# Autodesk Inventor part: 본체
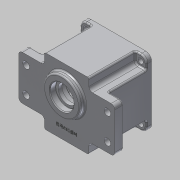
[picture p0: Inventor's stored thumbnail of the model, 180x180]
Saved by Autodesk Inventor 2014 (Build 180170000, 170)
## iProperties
Created: 2014-12
Part Number: 본체
Material: 알루미늄 6061
Document SubType Name: Modeling
Designer: user
Density: 2.71 g/cm^3
Appearance: 알루미늄 - 평지
Mass: 705.361 g
Surface Area: 672.962 cm^2
Volume: 260.281 cm^3
Author: user
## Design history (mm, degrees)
sketch "스케치2"
  geometry: L1 (-45, -45)-(45, -45); L2 (45, -45)-(45, 45); L3 (45, 45)-(-45, 45); L4 (-45, 45)-(-45, -45); L5 (-45, -45)-(45, 45); L6 (45, -45)-(-45, 45); 1 further point
  constraints: 12 end point, 2 midpoint, 2 parallel, 1 horizontal, 1 perpendicular
  dimensions: "d0" = 90 distance of L2.end L3.end; "d1" = 90 distance of L1.end L2.end
extrude "돌출1" new body sketch "스케치2" distance "d2" = 70; taper "d3" = 0 deg
sketch "스케치3"
  geometry: L1 (-65, -30)-(65, -30); L2 (65, -30)-(65, 30); L3 (65, 30)-(-65, 30); L4 (-65, 30)-(-65, -30); L5 (-65, -30)-(65, 30); L6 (65, -30)-(-65, 30); 1 further point
  constraints: 12 end point, 2 midpoint, 2 parallel, 1 horizontal, 1 perpendicular
  dimensions: "d4" = 130 distance of L2.end L3.end; "d5" = 60 distance of L1.end L2.end
extrude "돌출2" join sketch "스케치3" distance "d6" = 12; taper "d7" = 0 deg
sketch "스케치4"
  geometry: L1 (-45, 45)-(-30, 45); L2 (-30, 45)-(-30, 30); L3 (-30, 30)-(-45, 30); L4 (-45, 30)-(-45, 45); L5 (45, 45)-(30, 45); L6 (30, 45)-(30, 30); L7 (30, 30)-(45, 30); L8 (45, 30)-(45, 45); L9 (45, -45)-(30, -45); L10 (30, -45)-(30, -30); L11 (30, -30)-(45, -30); L12 (45, -30)-(45, -45); L13 (-45, -45)-(-30, -45); L14 (-30, -45)-(-30, -30); L15 (-30, -30)-(-45, -30); L16 (-45, -30)-(-45, -45); 1 further point
  constraints: 32 end point, 8 parallel, 4 horizontal, 4 perpendicular
  dimensions: "d8" = 15 distance of L1.start L1.end; "d9" = 15 distance of L1.end L2.end; "d10" = 15 distance of L5.start L5.end; "d11" = 15 distance of L5.end L6.end; "d12" = 15 distance of L11.end L9.start; "d13" = 15 distance of L9.start L9.end; "d14" = 15 distance of L13.start L13.end; "d15" = 15 distance of L15.end L13.start
extrude "돌출3" cut sketch "스케치4" distance "d16" = 63; taper "d17" = 0 deg
fillet "모깎기1" dims "d18" = 8
fillet "모깎기2" dims "d19" = 5
fillet "모깎기3" dims "d20" = 2
sketch "스케치5"
  geometry: L1 (-37, -37)-(37, -37); L2 (37, -37)-(37, 37); L3 (37, 37)-(-37, 37); L4 (-37, 37)-(-37, -37); L5 (-37, -37)-(37, 37); L6 (37, -37)-(-37, 37); 5 further points
  constraints: 12 end point, 4 coincident, 2 midpoint, 2 parallel, 1 horizontal, 1 perpendicular
  dimensions: "d21" = 74 distance of L2.end L3.end; "d22" = 74 distance of L1.end L2.end
hole "구멍1" sketch "스케치5" at (-37, 37), (37, 37), (37, -37), (-37, -37) diameter "d23" = 7; stored, may be unused: countersink angle "d27" = 90 deg, drill point angle "d29" = 118 deg; dims "d24" = 6, "d25" = 4, "d26" = 2, "d28" = 8
sketch "스케치6"
  geometry: L1 (-55, -17.5)-(55, -17.5); L2 (55, -17.5)-(55, 17.5); L3 (55, 17.5)-(-55, 17.5); L4 (-55, 17.5)-(-55, -17.5); L5 (-55, -17.5)-(55, 17.5); L6 (55, -17.5)-(-55, 17.5); 5 further points
  constraints: 12 end point, 4 coincident, 2 midpoint, 2 parallel, 1 horizontal, 1 perpendicular
  dimensions: "d30" = 110 distance of L2.end L3.end; "d31" = 35 distance of L1.end L2.end
hole "구멍2" sketch "스케치6" at (-55, 17.5), (-55, -17.5), (55, 17.5), (55, -17.5) diameter "d32" = 9; stored, may be unused: countersink angle "d36" = 90 deg, drill point angle "d38" = 118 deg; dims "d33" = 6, "d34" = 4, "d35" = 2, "d37" = 8
sketch "스케치7"
  geometry: C1 r 25 at (0, 11); 1 further point
  constraints: 1 centre point, 1 vertical alignment
  dimensions: "d39" = 50 diameter of C1; "d40" = 11 distance of point (0, 0) C1.centre
extrude "돌출4" join sketch "스케치7" distance "d41" = 7; taper "d42" = 0 deg
fillet "모깎기4" dims "d43" = 2
sketch "스케치8"
  geometry: C1 r 40 at (0, 0); 1 further point
  constraints: 1 centre point, 1 coincident
  dimensions: "d44" = 80 diameter of C1
extrude "돌출5" cut sketch "스케치8" distance "d45" = 9; taper "d46" = 0 deg
sketch "스케치9"
  geometry: C1 r 40 at (0, 0) reference; C2 r 39 at (0, 0)
  constraints: 1 centre point, 1 coincident
  dimensions: "d47" = 78 diameter of C2
extrude "돌출6" cut sketch "스케치9" distance "d48" = 52; taper "d49" = 0 deg
sketch "스케치10" dims "d50" = 70
  geometry: L1 (24.749, 24.749)-(-24.749, -24.749); L2 (-24.749, 24.749)-(24.749, -24.749); L3 (-35, 0)-(35, 0); C1 r 39 at (0, 0) reference; A1 r 4 centre (24.749, 24.749) between (21.809, 27.462) and (27.462, 21.809); A2 r 4 centre (-24.749, 24.749) between (-27.462, 21.809) and (-21.809, 27.462); A3 r 4 centre (24.749, -24.749) between (27.462, -21.809) and (21.809, -27.462); A4 r 4 centre (-24.749, -24.749) between (-21.809, -27.462) and (-27.462, -21.809); A5 r 3.5 centre (-19.238, -29.836) between (-15.988, -31.135) and (-21.762, -27.412); A6 r 3.5 centre (-29.836, -19.238) between (-31.135, -15.988) and (-32.777, -21.134); A7 r 3.5 centre (19.238, -29.836) between (15.988, -31.135) and (21.134, -32.777); A8 r 3.5 centre (29.836, -19.238) between (27.412, -21.762) and (32.777, -21.134); A9 r 3.5 centre (29.836, 19.238) between (31.135, 15.988) and (32.777, 21.134); A10 r 3.5 centre (19.238, 29.836) between (15.988, 31.135) and (21.762, 27.412); A11 r 3.5 centre (-19.238, 29.836) between (-21.134, 32.777) and (-21.762, 27.412); A12 r 3.5 centre (-29.836, 19.238) between (-27.412, 21.762) and (-32.777, 21.134); A13 r 3.5 centre (-19.238, 29.836) between (-15.988, 31.135) and (-21.134, 32.777); A14 r 3.5 centre (-19.238, 29.836) between (-21.762, 27.412) and (-15.988, 31.135); A15 r 4 centre (-24.749, 24.749) between (-27.577, 27.577) and (-27.462, 21.809); A16 r 3.5 centre (-29.836, 19.238) between (-31.135, 15.988) and (-27.412, 21.762); A17 r 3.5 centre (-29.836, 19.238) between (-32.777, 21.134) and (-31.135, 15.988); A18 r 39 centre (0, 0) between (-32.777, 21.134) and (-32.777, -21.134); A19 r 39 centre (0, 0) between (-21.134, 32.777) and (-32.777, 21.134); A20 r 3.5 centre (19.238, 29.836) between (21.134, 32.777) and (15.988, 31.135); A21 r 3.5 centre (19.238, 29.836) between (21.762, 27.412) and (21.134, 32.777); A22 r 4 centre (24.749, 24.749) between (27.577, 27.577) and (21.809, 27.462); A23 r 4 centre (24.749, 24.749) between (27.462, 21.809) and (27.577, 27.577); A24 r 3.5 centre (29.836, 19.238) between (27.412, 21.762) and (31.135, 15.988); A25 r 3.5 centre (29.836, 19.238) between (32.777, 21.134) and (27.412, 21.762); A26 r 3.5 centre (29.836, -19.238) between (31.135, -15.988) and (27.412, -21.762); A27 r 3.5 centre (29.836, -19.238) between (32.777, -21.134) and (31.135, -15.988); A28 r 4 centre (24.749, -24.749) between (27.577, -27.577) and (27.462, -21.809); A29 r 4 centre (24.749, -24.749) between (21.809, -27.462) and (27.577, -27.577); A30 r 3.5 centre (19.238, -29.836) between (21.762, -27.412) and (15.988, -31.135); A31 r 3.5 centre (19.238, -29.836) between (21.134, -32.777) and (21.762, -27.412); A32 r 39 centre (0, 0) between (21.134, -32.777) and (32.777, -21.134); A33 r 3.5 centre (-19.238, -29.836) between (-21.134, -32.777) and (-15.988, -31.135); A34 r 3.5 centre (-19.238, -29.836) between (-21.762, -27.412) and (-21.134, -32.777); A35 r 4 centre (-24.749, -24.749) between (-27.577, -27.577) and (-21.809, -27.462); A36 r 4 centre (-24.749, -24.749) between (-27.462, -21.809) and (-27.577, -27.577); A37 r 3.5 centre (-29.836, -19.238) between (-27.412, -21.762) and (-31.135, -15.988); A38 r 3.5 centre (-29.836, -19.238) between (-32.777, -21.134) and (-27.412, -21.762); A39 r 39 centre (0, 0) between (-21.134, -32.777) and (21.134, -32.777); A40 r 39 centre (0, 0) between (32.777, -21.134) and (39, 0); A41 r 39 centre (0, 0) between (32.777, 21.134) and (27.577, 27.577); A42 r 39 centre (0, 0) between (39, 0) and (32.777, 21.134); A43 r 39 centre (0, 0) between (27.577, 27.577) and (-21.134, 32.777); A44 r 4 centre (-24.749, 24.749) between (-21.809, 27.462) and (-27.577, 27.577); 3 further points
  constraints: 111 point on circle, 44 centre point, 16 tangent, 7 coincident, 6 end point, 4 midpoint, 1 horizontal, 1 point on line, 35 other
  dimensions: "d51" = 45 deg angle of L3 L1; "d52" = 90 deg angle of L2 L1; "d53" = 8 diameter of A1; "d54" = 8 diameter of A2; "d57" = 8 diameter of A3; "d58" = 8 diameter of A4; "d59" = 7 diameter of A6; "d60" = 7 diameter of A5; "d61" = 7 diameter of A7; "d62" = 7 diameter of A8; "d63" = 7 diameter of A9; "d64" = 7 diameter of A10; "d65" = 7 diameter of A11; "d66" = 7 diameter of A12
extrude "돌출7" join sketch "스케치10" distance "d67" = 52; taper "d68" = 0 deg
sketch "스케치11"
  geometry: A1 r 4 centre (24.749, -24.749) between (27.462, -21.809) and (21.809, -27.462) reference; A2 r 4 centre (-24.749, -24.749) between (-21.809, -27.462) and (-27.462, -21.809) reference; A3 r 4 centre (-24.749, 24.749) between (-27.462, 21.809) and (-21.809, 27.462) reference; A4 r 4 centre (24.749, 24.749) between (21.809, 27.462) and (27.462, 21.809) reference; 4 further points
  constraints: 4 coincident
hole "구멍3" sketch "스케치11" at (-24.749, 24.749), (24.749, 24.749), (24.749, -24.749), (-24.749, -24.749) diameter "d69" = 3.459; stored, may be unused: countersink angle "d73" = 90 deg, drill point angle "d75" = 118 deg; dims "d70" = 12, "d71" = 4, "d72" = 2, "d74" = 15
sketch "스케치12"
  geometry: A1 r 39 centre (0, 0) between (-32.777, 21.134) and (-32.777, -21.134) reference; A2 r 20.5 centre (0, -11) between (-7.402, 8.117) and (7.402, 8.117); A3 r 14 centre (0, 20) between (7.402, 8.117) and (-7.402, 8.117); A4 r 14 centre (0, 20) between (-7.402, 8.117) and (7.402, 8.117); A5 r 20.5 centre (0, -11) between (7.402, 8.117) and (-7.402, 8.117)
  constraints: 8 point on circle, 4 centre point, 2 vertical alignment
  dimensions: "d76" = 41 diameter of A2; "d77" = 28 diameter of A3; "d78" = 11 distance of A1.centre A2.centre; "d79" = 20 distance of A1.centre A3.centre
extrude "돌출8" join sketch "스케치12" distance "d80" = 7; taper "d81" = 0 deg
fillet "모깎기5" dims "d82" = 3
sketch "스케치13"
  geometry: C1 r 17.5 at (0, -11); A1 r 20.5 centre (0, -11) between (-11.115, 6.225) and (11.115, 6.225) reference; 1 further point
  constraints: 1 centre point, 1 coincident
  dimensions: "d83" = 35 diameter of C1
extrude "돌출9" cut sketch "스케치13" distance "d84" = 10; taper "d85" = 0 deg
sketch "스케치14"
  geometry: C1 r 17.5 at (0, 0) reference; C2 r 12.5 at (0, 0); 1 further point
  constraints: 1 centre point, 1 coincident
  dimensions: "d86" = 25 diameter of C2
extrude "돌출10" cut sketch "스케치14" distance "d87" = 5; taper "d88" = 0 deg
sketch "스케치15"
  geometry: C1 r 23 at (0, 0) reference; C2 r 16 at (0, 0); 1 further point
  constraints: 1 centre point, 1 coincident
  dimensions: "d89" = 32 diameter of C2
extrude "돌출11" cut sketch "스케치15" distance "d90" = 8; taper "d91" = 0 deg
chamfer "모따기1" distance "d92" = 1; stored, may be unused: second distance "d93" = 2, angle "d94" = 45 deg
fillet "모깎기6" dims "d95" = 0.3
sketch "스케치16"
  geometry: C1 r 11 at (0, 20); A1 r 14 centre (0, 20) between (10.493, 10.732) and (-10.493, 10.732) reference; 1 further point
  constraints: 1 centre point, 1 coincident
  dimensions: "d96" = 22 diameter of C1
extrude "돌출12" cut sketch "스케치16" distance "d97" = 7; taper "d98" = 0 deg
sketch "스케치17"
  geometry: C1 r 11 at (0, 0) reference; C2 r 9.5 at (0, 0); 1 further point
  constraints: 1 centre point, 1 coincident
  dimensions: "d99" = 19 diameter of C2
extrude "돌출13" cut sketch "스케치17" distance "d100" = 1; taper "d101" = 0 deg
fillet "모깎기7" dims "d102" = 2
fillet "모깎기8" dims "d103" = 0.3
fillet "모깎기9" dims "d104" = 2
chamfer "모따기2" distance "d105" = 1; stored, may be unused: second distance "d106" = 2, angle "d107" = 45 deg
sketch "스케치18"
  geometry: L1 (-28, -45)-(28, -45) reference; C1 r 27 at (0, 11) reference; 2 further points
  constraints: 1 vertical alignment, 1 other
  dimensions: "d108" = 15 distance from line of L1 point (0, -30)
feature "엠보싱1" sketch "스케치18" dims "d0" = 90, "d1" = 90, "d109" = 0.5, "d110" = 0
node "솔리드1"
